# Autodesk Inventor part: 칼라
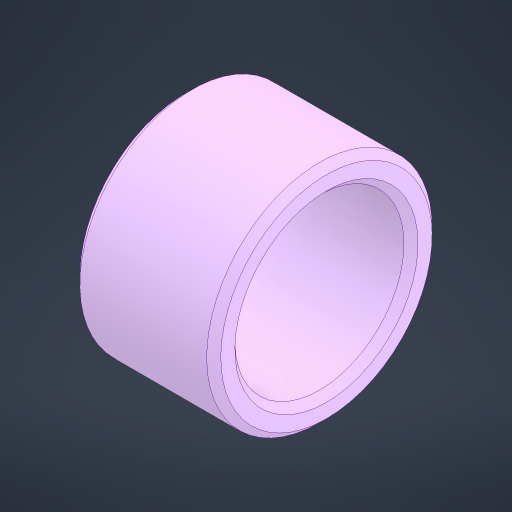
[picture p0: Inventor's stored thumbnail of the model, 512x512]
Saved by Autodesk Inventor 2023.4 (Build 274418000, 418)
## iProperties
Created: 2024-05
Part Number: 칼라
Material: 강철, 합금
Document SubType Name: Modeling
Designer: Edu03
Density: 7.73 g/cm^3
Appearance: 기본값
Sending System: Autodesk Inventor 2025
Preprocessor: ST-DEVELOPER v20
Author: jhkim
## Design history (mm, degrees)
node "칼라1"
node "솔리드2"
node "솔리드1"
